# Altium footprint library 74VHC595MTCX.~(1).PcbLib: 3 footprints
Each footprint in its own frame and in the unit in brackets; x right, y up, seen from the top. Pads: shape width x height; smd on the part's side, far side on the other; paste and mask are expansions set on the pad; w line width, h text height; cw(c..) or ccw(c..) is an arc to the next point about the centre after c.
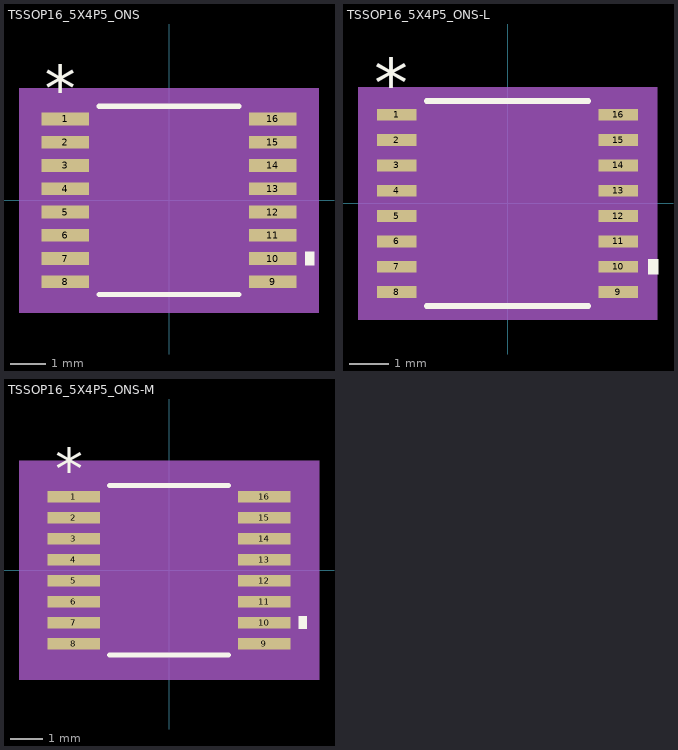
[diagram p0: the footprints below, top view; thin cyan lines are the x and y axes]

## TSSOP16_5X4P5_ONS [mil]
pads (16):
  rect 52x14 smd paste+0 mask+0: 1(-114,89.57) 2(-114,63.98) 3(-114,38.39) 4(-114,12.8) 5(-114,-12.8) 6(-114,-38.39) 7(-114,-63.98) 8(-114,-89.57) 9(114,-89.57) 10(114,-63.98) 11(114,-38.39) 12(114,-12.8) 13(114,12.8) 14(114,38.39) 15(114,63.98) 16(114,89.57)
Top Overlay:
  region: 150,-56.48 160,-56.48 160,-71.48 150,-71.48
  lines w6: -76.89,-103.5 76.89,-103.5 ; -76.89,103.5 76.89,103.5
  text "*" at -136.5,98.57 h50
Mechanical 5:
  region: 165,-123.5 -165,-123.5 -165,123.5 165,123.5
Mechanical 13:
  lines w0: -12,98.5 ccw(c0,98.5) 12,98.5
  lines w1: -126,-95.57 -126,-83.57 -86.5,-83.57 -86.5,-95.57 -126,-95.57 ; -126,-69.98 -126,-57.98 -86.5,-57.98 -86.5,-69.98 -126,-69.98 ; -126,-44.39 -126,-32.39 -86.5,-32.39 -86.5,-44.39 -126,-44.39 ; -126,-18.8 -126,-6.8 -86.5,-6.8 -86.5,-18.8 -126,-18.8 ; -126,6.8 -126,18.8 -86.5,18.8 -86.5,6.8 -126,6.8 ; -126,32.39 -126,44.39 -86.5,44.39 -86.5,32.39 -126,32.39 ; -126,57.98 -126,69.98 -86.5,69.98 -86.5,57.98 -126,57.98 ; -126,83.57 -126,95.57 -86.5,95.57 -86.5,83.57 -126,83.57 ; -86.5,-98.5 86.5,-98.5 86.5,98.5 -86.5,98.5 -86.5,-98.5 ; 86.5,-95.57 86.5,-83.57 126,-83.57 126,-95.57 86.5,-95.57 ; 86.5,-69.98 86.5,-57.98 126,-57.98 126,-69.98 86.5,-69.98 ; 86.5,-44.39 86.5,-32.39 126,-32.39 126,-44.39 86.5,-44.39 ; 86.5,-18.8 86.5,-6.8 126,-6.8 126,-18.8 86.5,-18.8 ; 86.5,6.8 86.5,18.8 126,18.8 126,6.8 86.5,6.8 ; 86.5,32.39 86.5,44.39 126,44.39 126,32.39 86.5,32.39 ; 86.5,57.98 86.5,69.98 126,69.98 126,57.98 86.5,57.98 ; 86.5,83.57 86.5,95.57 126,95.57 126,83.57 86.5,83.57
  text "*" at -84,45.5 h50
Mechanical 15:
  region: -96.5,-106.57 -150,-106.57 -150,106.57 -96.5,106.57 -96.5,108.5 96.5,108.5 96.5,106.57 150,106.57 150,-106.57 96.5,-106.57 96.5,-108.5 -96.5,-108.5
  lines w6: -150,-106.57 -150,106.57 -96.5,106.57 -96.5,108.5 96.5,108.5 96.5,106.57 150,106.57 150,-106.57 96.5,-106.57 96.5,-108.5 -96.5,-108.5 -96.5,-106.57 -150,-106.57
3D body "TSSOP16_5X4P5_ONS.step": height 35.12, standoff 0, extent -125.98,-98.5 125.98,98.5

## TSSOP16_5X4P5_ONS-L [mil]
pads (16):
  rect 40x12 smd paste+0 mask+0: 1(-112,89.57) 2(-112,63.98) 3(-112,38.39) 4(-112,12.8) 5(-112,-12.8) 6(-112,-38.39) 7(-112,-63.98) 8(-112,-89.57) 9(112,-89.57) 10(112,-63.98) 11(112,-38.39) 12(112,-12.8) 13(112,12.8) 14(112,38.39) 15(112,63.98) 16(112,89.57)
Top Overlay:
  region: 142,-56.48 152,-56.48 152,-71.48 142,-71.48
  lines w6: -81.58,-103.5 81.58,-103.5 ; -81.58,103.5 81.58,103.5
  text "*" at -134.5,96.57 h50
Mechanical 5:
  region: 151,-117.5 -151,-117.5 -151,117.5 151,117.5
Mechanical 13:
  lines w0: -12,98.5 ccw(c0,98.5) 12,98.5
  lines w1: -126,-95.57 -126,-83.57 -86.5,-83.57 -86.5,-95.57 -126,-95.57 ; -126,-69.98 -126,-57.98 -86.5,-57.98 -86.5,-69.98 -126,-69.98 ; -126,-44.39 -126,-32.39 -86.5,-32.39 -86.5,-44.39 -126,-44.39 ; -126,-18.8 -126,-6.8 -86.5,-6.8 -86.5,-18.8 -126,-18.8 ; -126,6.8 -126,18.8 -86.5,18.8 -86.5,6.8 -126,6.8 ; -126,32.39 -126,44.39 -86.5,44.39 -86.5,32.39 -126,32.39 ; -126,57.98 -126,69.98 -86.5,69.98 -86.5,57.98 -126,57.98 ; -126,83.57 -126,95.57 -86.5,95.57 -86.5,83.57 -126,83.57 ; -86.5,-98.5 86.5,-98.5 86.5,98.5 -86.5,98.5 -86.5,-98.5 ; 86.5,-95.57 86.5,-83.57 126,-83.57 126,-95.57 86.5,-95.57 ; 86.5,-69.98 86.5,-57.98 126,-57.98 126,-69.98 86.5,-69.98 ; 86.5,-44.39 86.5,-32.39 126,-32.39 126,-44.39 86.5,-44.39 ; 86.5,-18.8 86.5,-6.8 126,-6.8 126,-18.8 86.5,-18.8 ; 86.5,6.8 86.5,18.8 126,18.8 126,6.8 86.5,6.8 ; 86.5,32.39 86.5,44.39 126,44.39 126,32.39 86.5,32.39 ; 86.5,57.98 86.5,69.98 126,69.98 126,57.98 86.5,57.98 ; 86.5,83.57 86.5,95.57 126,95.57 126,83.57 86.5,83.57
  text "*" at -84,45.5 h50
Mechanical 15:
  region: -90.5,-99.57 -136,-99.57 -136,99.57 -90.5,99.57 -90.5,102.5 90.5,102.5 90.5,99.57 136,99.57 136,-99.57 90.5,-99.57 90.5,-102.5 -90.5,-102.5
  lines w6: -136,-99.57 -136,99.57 -90.5,99.57 -90.5,102.5 90.5,102.5 90.5,99.57 136,99.57 136,-99.57 90.5,-99.57 90.5,-102.5 -90.5,-102.5 -90.5,-99.57 -136,-99.57
3D body "TSSOP16_5X4P5_ONS.step": height 35.12, standoff 0, extent -125.98,-98.5 125.98,98.5

## TSSOP16_5X4P5_ONS-M [mil]
pads (16):
  rect 64x14 smd paste+0 mask+0: 1(-116,89.57) 2(-116,63.98) 3(-116,38.39) 4(-116,12.8) 5(-116,-12.8) 6(-116,-38.39) 7(-116,-63.98) 8(-116,-89.57) 9(116,-89.57) 10(116,-63.98) 11(116,-38.39) 12(116,-12.8) 13(116,12.8) 14(116,38.39) 15(116,63.98) 16(116,89.57)
Top Overlay:
  region: 158,-56.48 168,-56.48 168,-71.48 158,-71.48
  lines w6: -72.89,-103.5 72.89,-103.5 ; -72.89,103.5 72.89,103.5
  text "*" at -138.5,98.57 h50
Mechanical 5:
  region: 183,-133.5 -183,-133.5 -183,133.5 183,133.5
Mechanical 13:
  lines w0: -12,98.5 ccw(c0,98.5) 12,98.5
  lines w1: -126,-95.57 -126,-83.57 -86.5,-83.57 -86.5,-95.57 -126,-95.57 ; -126,-69.98 -126,-57.98 -86.5,-57.98 -86.5,-69.98 -126,-69.98 ; -126,-44.39 -126,-32.39 -86.5,-32.39 -86.5,-44.39 -126,-44.39 ; -126,-18.8 -126,-6.8 -86.5,-6.8 -86.5,-18.8 -126,-18.8 ; -126,6.8 -126,18.8 -86.5,18.8 -86.5,6.8 -126,6.8 ; -126,32.39 -126,44.39 -86.5,44.39 -86.5,32.39 -126,32.39 ; -126,57.98 -126,69.98 -86.5,69.98 -86.5,57.98 -126,57.98 ; -126,83.57 -126,95.57 -86.5,95.57 -86.5,83.57 -126,83.57 ; -86.5,-98.5 86.5,-98.5 86.5,98.5 -86.5,98.5 -86.5,-98.5 ; 86.5,-95.57 86.5,-83.57 126,-83.57 126,-95.57 86.5,-95.57 ; 86.5,-69.98 86.5,-57.98 126,-57.98 126,-69.98 86.5,-69.98 ; 86.5,-44.39 86.5,-32.39 126,-32.39 126,-44.39 86.5,-44.39 ; 86.5,-18.8 86.5,-6.8 126,-6.8 126,-18.8 86.5,-18.8 ; 86.5,6.8 86.5,18.8 126,18.8 126,6.8 86.5,6.8 ; 86.5,32.39 86.5,44.39 126,44.39 126,32.39 86.5,32.39 ; 86.5,57.98 86.5,69.98 126,69.98 126,57.98 86.5,57.98 ; 86.5,83.57 86.5,95.57 126,95.57 126,83.57 86.5,83.57
  text "*" at -84,45.5 h50
Mechanical 15:
  region: -106.5,-116.57 -168,-116.57 -168,116.57 -106.5,116.57 -106.5,118.5 106.5,118.5 106.5,116.57 168,116.57 168,-116.57 106.5,-116.57 106.5,-118.5 -106.5,-118.5
  lines w6: -168,-116.57 -168,116.57 -106.5,116.57 -106.5,118.5 106.5,118.5 106.5,116.57 168,116.57 168,-116.57 106.5,-116.57 106.5,-118.5 -106.5,-118.5 -106.5,-116.57 -168,-116.57
3D body "TSSOP16_5X4P5_ONS.step": height 35.12, standoff 0, extent -125.98,-98.5 125.98,98.5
